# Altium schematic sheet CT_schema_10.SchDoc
size 391 x 238 mm
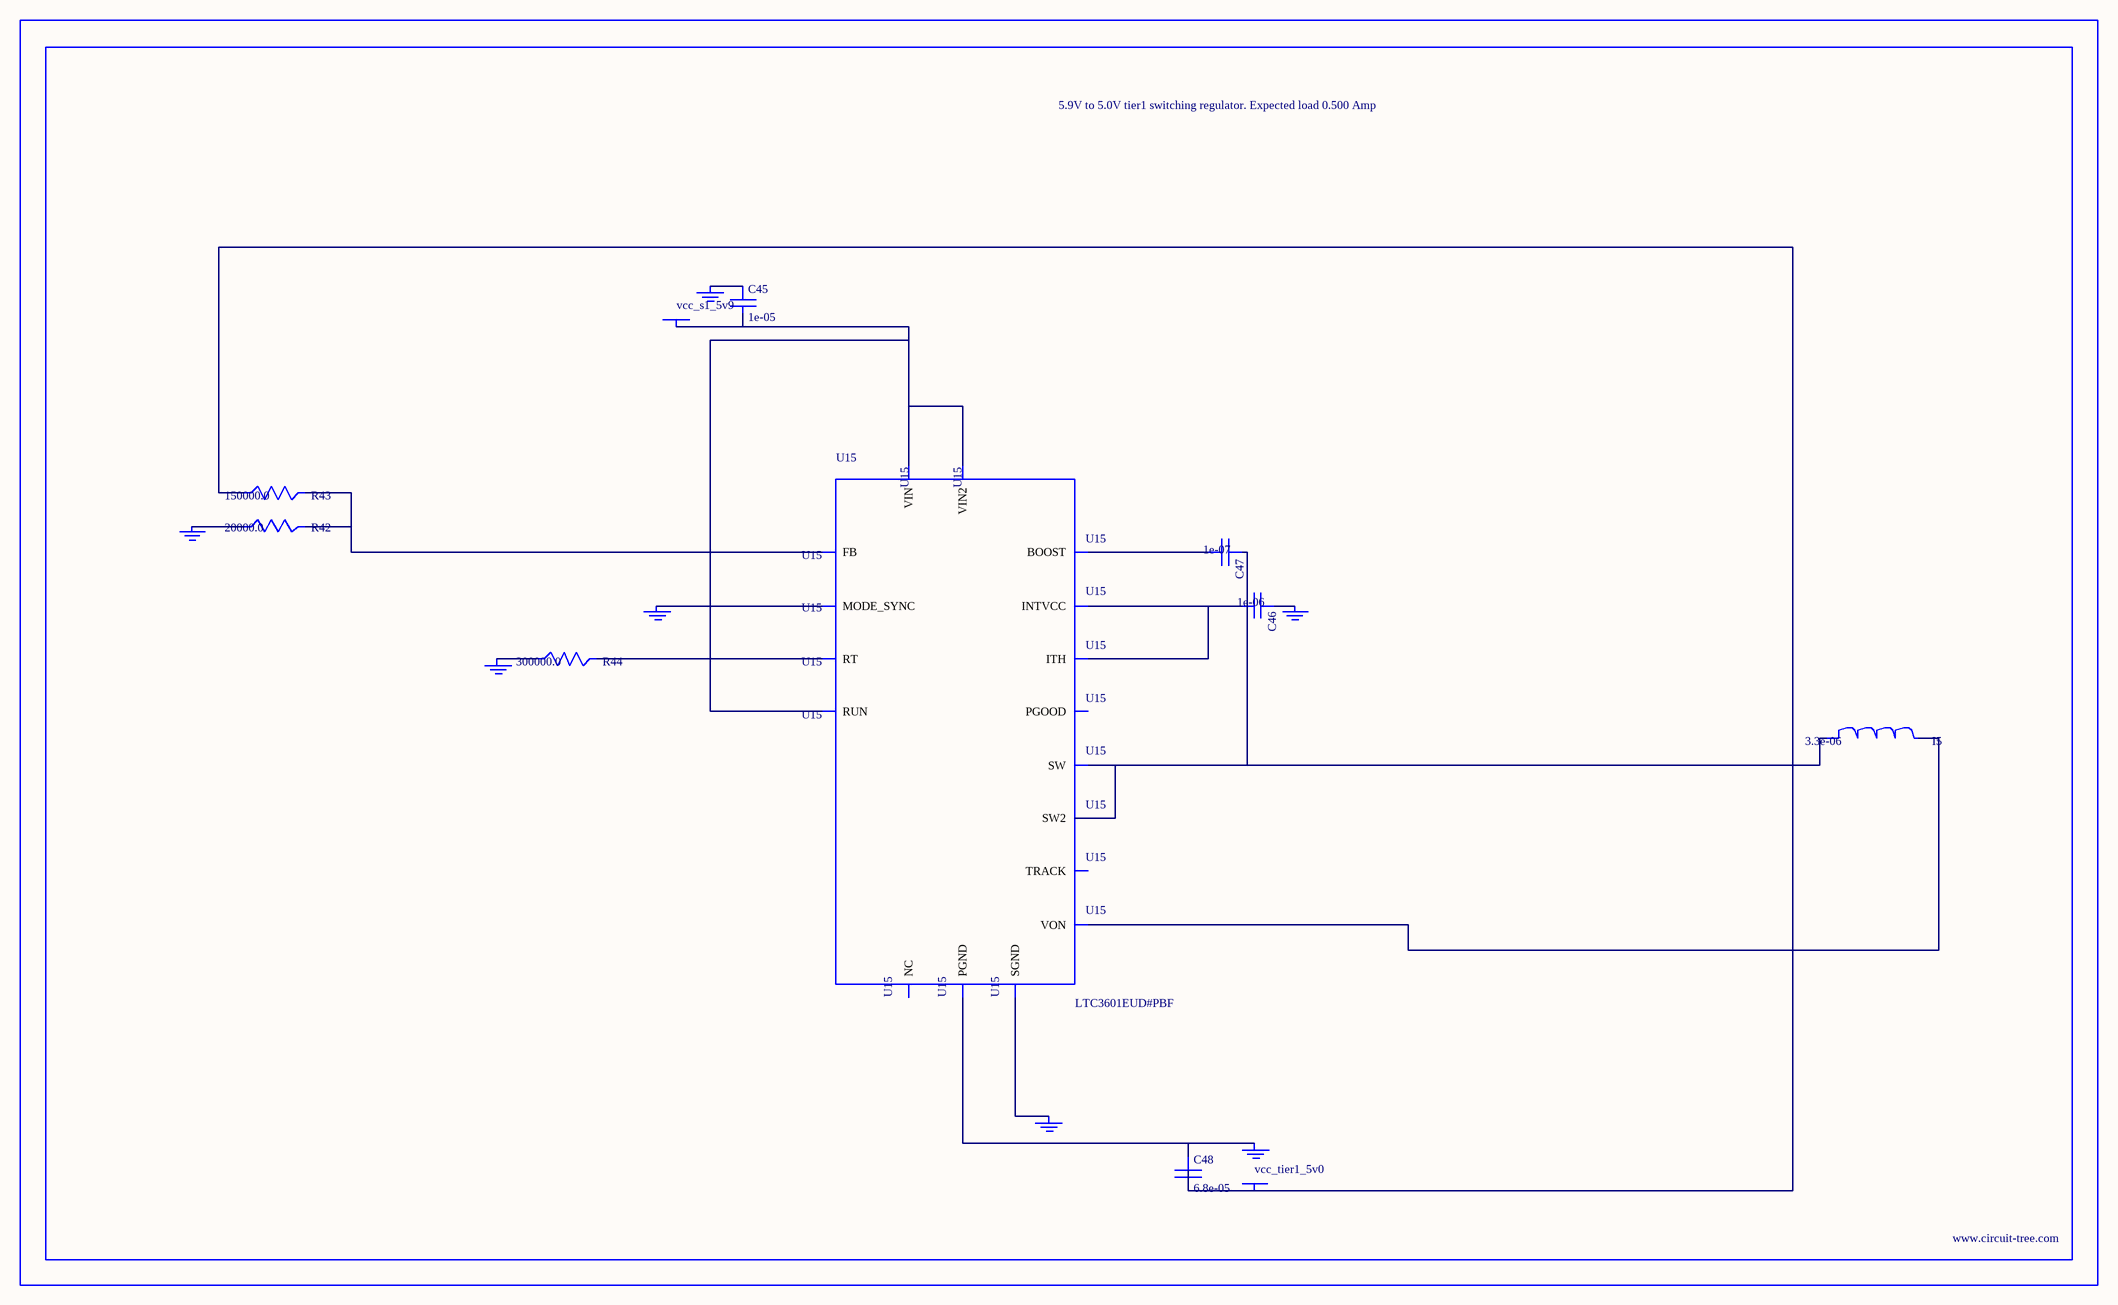
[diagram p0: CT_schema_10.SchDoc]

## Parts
BORDER9  (no value)
C45  1e-05  [C0805]
C46  1e-06  [C0603]
C47  1e-07  [C0402]
C48  6.8e-05  [2220]
GND_INSTANCE_9_0  (no value)
GND_INSTANCE_9_1  (no value)
GND_INSTANCE_9_2  (no value)
GND_INSTANCE_9_3  (no value)
GND_INSTANCE_9_4  (no value)
GND_INSTANCE_9_5  (no value)
GND_INSTANCE_9_6  (no value)
I5  3.3e-06  [WE-HCI_7030/7040/7050]
POWER_INSTANCE_9_0  vcc_s1_5v9
POWER_INSTANCE_9_1  vcc_tier1_5v0
R42  20000.0  [R0603]
R43  150000.0  [R0603]
R44  300000.0  [R0603]
U15  LTC3601EUD#PBF  [QFN-16_EP]

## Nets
NetC45_1: C45.1 GND_INSTANCE_9_5.0(GND)
NetC45_2: C45.2 POWER_INSTANCE_9_0.0(PWR) U15.14(RUN) U15.15(VIN) U15.16(VIN2)
NetC46_1: C46.1 GND_INSTANCE_9_1.0(GND)
NetC46_2: C46.2 U15.7(INTVCC) U15.12(ITH)
NetC47_1: C47.1 I5.1 U15.3(SW) U15.4(SW2)
NetC47_2: C47.2 U15.6(BOOST)
NetC48_1: C48.1 GND_INSTANCE_9_6.0(GND) U15.17(PGND)
NetC48_2: C48.2 I5.2 POWER_INSTANCE_9_1.0(PWR) R43.1 U15.8(VON)
NetGND_INSTANCE_9_0_0: GND_INSTANCE_9_0.0(GND) U15.1(MODE_SYNC)
NetGND_INSTANCE_9_2_0: GND_INSTANCE_9_2.0(GND) U15.9(SGND)
NetGND_INSTANCE_9_3_0: GND_INSTANCE_9_3.0(GND) R44.1
NetGND_INSTANCE_9_4_0: GND_INSTANCE_9_4.0(GND) R42.1
NetR42_2: R42.2 R43.2 U15.11(FB)
NetR44_2: R44.2 U15.10(RT)

Not connected (* = marked no-connect by the designer): U15 2(PGOOD) 5(NC) 13(TRACK)

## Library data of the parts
BORDER9 = BORDER_PAGE9
C45 = C0805C106K8RACTU
C46 = C0603C105K3RACTU
C47 = C0402C104K3RACTU
C48 = C5750X5R1A686M
GND_INSTANCE_9_0-GND_INSTANCE_9_6 = GND
I5 = 744314330
POWER_INSTANCE_9_0 POWER_INSTANCE_9_1 = PWR
R42 = RC0603JR-0720KL
R43 = RC0603JR-07150KL
R44 = RC0603JR-07300KL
